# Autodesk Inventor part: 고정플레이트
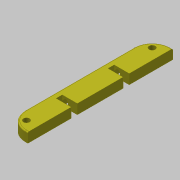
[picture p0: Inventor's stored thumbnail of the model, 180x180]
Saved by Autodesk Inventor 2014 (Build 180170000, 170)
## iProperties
Created: 2018-08
Part Number: 고정플레이트
Material: ABS 플라스틱
Document SubType Name: Modeling
Designer: mduedu
Density: 1 g/cm^3
Appearance: 밝은 황색
Author: mduedu
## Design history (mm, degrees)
sketch "스케치1"
  geometry: L1 (0, -60)-(17, -60); L2 (17, -60)-(17, 60); L3 (17, 60)-(0, 60); L4 (0, 60)-(0, -60); 2 further points
  constraints: 8 end point, 2 parallel, 1 coincident, 1 horizontal, 1 midpoint, 1 perpendicular
  dimensions: "d0" = 120 distance between parallel lines of L3 L1; "d2" = 17 distance of L1.start L1.end
extrude "돌출1" new body sketch "스케치1" distance "d3" = 8; taper "d4" = 0 deg
fillet "모깎기1" dims "d5" = 15
fillet "모깎기2" dims "d6" = 1
sketch "스케치2"
  geometry: L1 (-17, 0)-(-17, 7) reference; L2 (0, 0)-(-17, 0) reference; L3 (-12.5, 4)-(-12.5, 0); L4 (-7.5, 4)-(-7.5, 0); A1 r 2.5 centre (-10, 4) between (-12.5, 4) and (-7.5, 4)
  constraints: 4 end point, 2 perpendicular, 2 point on circle, 2 point on line, 2 tangent, 1 centre point
  dimensions: "d7" = 5 diameter of A1; "d8" = 7 distance from line of A1.centre L1; "d9" = 4 distance from line of L2 A1.centre
extrude "돌출2" cut sketch "스케치2" stored distance "d10" = 70; taper "d11" = 0 deg
fillet "모깎기3" dims "d12" = 2.5
sketch "스케치3"
  geometry: L1 (-12.5, -19)-(0, -19); L2 (0, -19)-(0, -24); L3 (0, -24)-(-12.5, -24); L4 (-12.5, -24)-(-12.5, -19); L5 (0, -59)-(0, 59) reference; L6 (-17, 45)-(-17, -45) reference; 2 further points
  constraints: 8 end point, 2 parallel, 1 horizontal, 1 midpoint, 1 perpendicular, 1 vertical alignment
  dimensions: "d13" = 4.5 distance between parallel lines of L4 L6; "d14" = 19 distance from line of L1 point (0, 0); "d15" = 5 distance of L1.end L2.end
extrude "돌출3" cut sketch "스케치3" stored distance "d16" = 70; taper "d17" = 0 deg
sketch "스케치4"
  geometry: A1 r 15 centre (-2, -45) between (-17, -45) and (-2, -60) reference; A2 r 15 centre (-2, 45) between (-2, 60) and (-17, 45) reference; A3 r 10 centre (-2, 45) between (-2, 55) and (-12, 45); A4 r 10 centre (-2, -45) between (-12, -45) and (-2, -55); 3 further points
  constraints: 6 point on circle, 2 centre point, 2 horizontal alignment, 2 vertical alignment
  dimensions: "d18" = 5 radial gap between concentric circles of A3 A2; "d19" = 5 radial gap between concentric circles of A1 A4
hole "구멍1" sketch "스케치4" at (-9.071, 52.071), (-9.071, -52.071) diameter "d20" = 5; stored, may be unused: countersink angle "d24" = 90 deg, drill point angle "d26" = 118 deg; dims "d21" = 6, "d22" = 4, "d23" = 2, "d25" = 8
node "솔리드1"
mirror "대칭1"
